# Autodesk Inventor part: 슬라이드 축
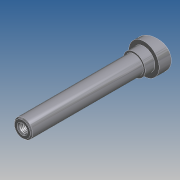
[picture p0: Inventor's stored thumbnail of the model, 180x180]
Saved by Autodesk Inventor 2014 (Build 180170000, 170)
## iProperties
Created: 2012-05
Part Number: 슬라이드 축
Document SubType Name: 모델링
Designer: SeoGD™
Mass: 19.8501 g
Surface Area: 63.0734 cm^2
Volume: 19.8501 cm^3
Density: 1 g/cm^3
Material: 일반
Appearance: 기본값
변환 표준: STEP AP214IS
파일 이름: C:\Users\SeoGD\Desktop\?쒗뿕\異?stp
전처리기: Build: 253, Release: 2010 SP1 - Date: Wed 07/29/2009
전송 단위: 밀리미터
불확실성: 0.01
Author: SeoGD™
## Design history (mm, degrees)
sketch "스케치1"
  geometry: L1 (0, 100)-(7.5, 100); L2 (7.5, 100)-(7.5, 0); L3 (7.5, 0)-(12.5, 0); L4 (12.5, 0)-(12.5, -17); L5 (12.5, -17)-(0, -17); L6 (0, -17)-(0, 100); 1 further point
  constraints: 12 end point, 2 parallel, 2 point on line, 1 perpendicular, 1 vertical
  dimensions: "d0" = 100 distance from line of L1 point (0, 0); "d1" = 15 diameter of L2 L6; "d2" = 25 diameter of L4 L6; "d3" = 17 distance of L3.end L4.end
revolve "회전1" sketch "스케치1" stored, may be unused: angle "d4" = 90 deg
sketch "스케치2"
  geometry: L1 (12.5, 0)-(12.5, -17) reference; L2 (-12.5, -17)-(12.5, -17) reference; L3 (-12.5, 0)-(-12.5, -17) reference; L4 (12.5, -5)-(-12.5, -11.699); L5 (-12.5, 0)-(12.5, 0) reference; 1 further point
  constraints: 2 end point, 2 point on line
  dimensions: "d5" = 75 deg angle of L1 L4; "d6" = 5 distance from line of L4.start L5
extrude "돌출1" cut sketch "스케치2" stored distance "d7" = 10; taper "d8" = 0 deg
chamfer "모따기1" distance "d9" = 1; stored, may be unused: second distance "d10" = 2, angle "d11" = 45 deg
fillet "모깎기1" dims "d12" = 0.5
hole "구멍1" diameter "d15" = 6.647; stored, may be unused: countersink angle "d19" = 90 deg, drill point angle "d21" = 118 deg; dims "d13" = 10, "d14" = 10, "d16" = 17, "d17" = 4, "d18" = 2, "d20" = 20
chamfer "모따기2" distance "d22" = 1; stored, may be unused: second distance "d23" = 2, angle "d24" = 45 deg
sketch "스케치3"
  geometry: C1 r 9 at (0, 0); 1 further point
  constraints: 1 centre point, 1 coincident
  dimensions: "d25" = 18 diameter of C1
extrude "돌출2" join sketch "스케치3" distance "d26" = 8; taper "d27" = 0 deg
node "솔리드1"
node "솔리드 본체"
node "곡면 본체"
node "솔리드2"
